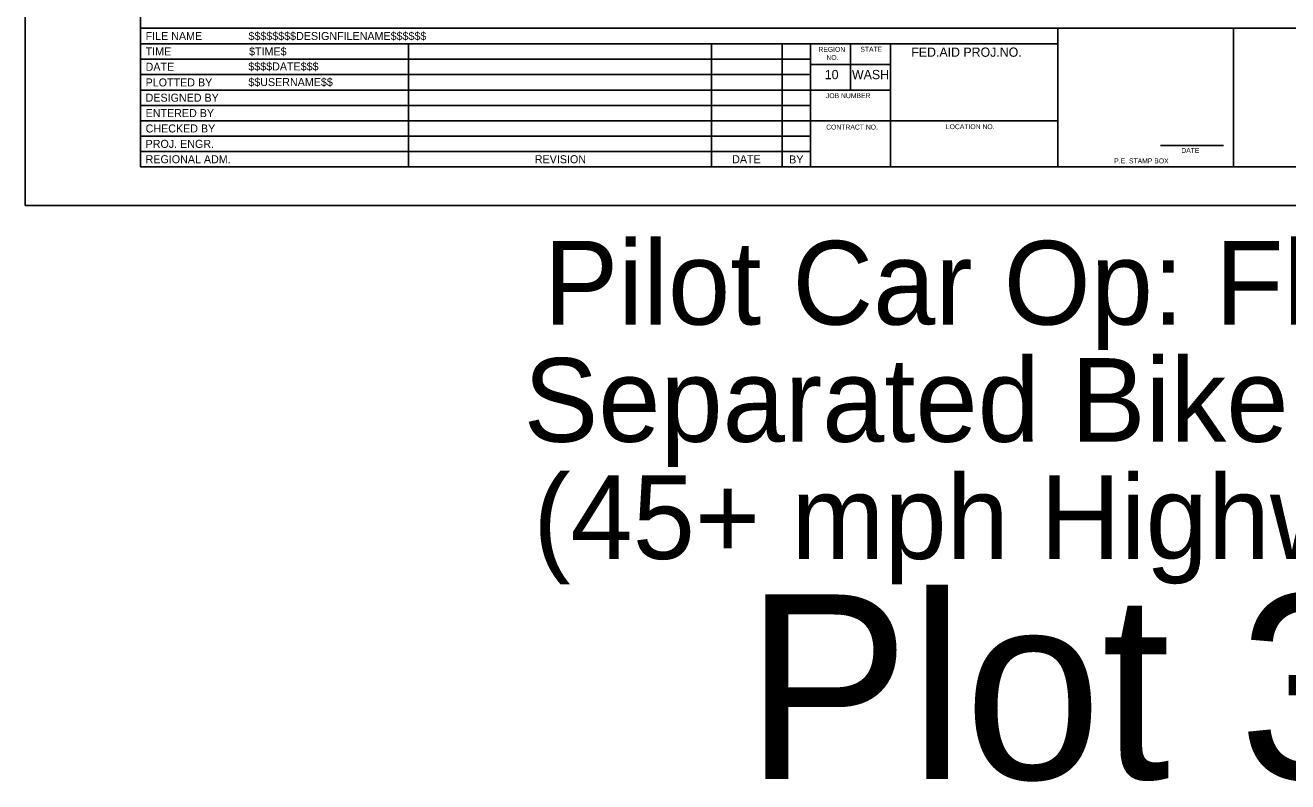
# Model space of a CAD drawing. Extents: x 99999.1 to 100095.7, y 99995 to 100010.7.
# Drawn here: x 100039.06 to 100049.33, y 99995.01 to 100001.15 of the extents above; entities that cross this region are included whole.
import ezdxf

# ---------------------------------------------------------------- set-up
doc = ezdxf.new("R2010")
doc.units = 0
for name, color, linetype in [('SH_GI_PlotLimits', 7, 'Continuous'), ('SH_GI_SheetBorder', 7, 'Continuous'), ('SH_GI_SheetLocationText', 7, 'Continuous'), ('SH_GI_SheetTextInCells', 7, 'Continuous'), ('SH_GI_TitleBlockText', 7, 'Continuous')]:
    doc.layers.add(name, color=color, linetype=linetype)

msp = doc.modelspace()

# ---------------------------------------------------------------- linework, layer by layer
at = {"layer": 'SH_GI_PlotLimits'}
msp.add_lwpolyline([(100039.062, 99999.687), (100056.062, 99999.687), (100056.062, 100010.687), (100039.062, 100010.687)], close=True, dxfattribs=at)
at = {"layer": 'SH_GI_SheetBorder'}
for p, q in [((100040, 100010.375), (100040, 100000)), ((100040, 100001.126), (100055.75, 100001.126)), ((100047.457, 100000), (100047.457, 100001.126)), ((100048.883, 100000), (100048.883, 100001.126)), ((100040, 100001.001), (100047.457, 100001.001)), ((100042.179, 100001.001), (100042.179, 100000)), ((100044.641, 100001.001), (100044.641, 100000)), ((100045.216, 100001.001), (100045.216, 100000)), ((100045.445, 100001.001), (100045.445, 100000)), ((100045.772, 100000.625), (100045.772, 100001.001)), ((100046.096, 100000), (100046.096, 100001.001)), ((100040, 100000.876), (100042.182, 100000.876)), ((100042.182, 100000.876), (100045.447, 100000.876)), ((100046.096, 100000.831), (100045.447, 100000.831)), ((100040, 100000.751), (100042.182, 100000.751)), ((100042.182, 100000.751), (100045.447, 100000.751)), ((100040, 100000.625), (100045.447, 100000.625)), ((100046.096, 100000.625), (100045.447, 100000.625)), ((100040, 100000.5), (100045.447, 100000.5)), ((100040, 100000.375), (100045.447, 100000.375)), ((100047.457, 100000.375), (100045.447, 100000.375)), ((100040, 100000.25), (100045.447, 100000.25)), ((100040, 100000.125), (100045.447, 100000.125)), ((100048.29, 100000.173), (100048.802, 100000.173)), ((100040, 100000), (100055.75, 100000))]:
    msp.add_line(p, q, dxfattribs=at)

# ---------------------------------------------------------------- texts
at = {"layer": 'SH_GI_SheetLocationText'}
for s, height, p in [('Pilot Car Op: Flagger', 0.68, (100043.277, 99998.719)), ('Separated Bike Lane', 0.68, (100043.114, 99997.767)), ('(45+ mph Highways)', 0.68, (100043.192, 99996.815)), ('Plot 3', 1.5, (100044.913, 99995.027))]:
    msp.add_text(s, height=height, dxfattribs=at).set_placement(p)
at = {"layer": 'SH_GI_SheetTextInCells'}
for s, height, p in [('FILE NAME', 0.0651, (100040.041, 100001.031)), ('TIME', 0.0651, (100040.041, 100000.906)), ('REGION', 0.04, (100045.51, 100000.935)), ('STATE', 0.04, (100045.851, 100000.936)), ('FED.AID PROJ.NO.', 0.07506, (100046.265, 100000.895)), ('DATE', 0.0651, (100040.041, 100000.781)), ('NO.', 0.04, (100045.575, 100000.869)), ('PLOTTED BY', 0.0651, (100040.041, 100000.654)), ('10', 0.0751, (100045.562, 100000.713)), ('WASH', 0.0751, (100045.783, 100000.713)), ('DESIGNED BY', 0.06505, (100040.041, 100000.53)), ('JOB NUMBER', 0.04, (100045.571, 100000.559)), ('ENTERED BY', 0.0651, (100040.041, 100000.405)), ('CHECKED BY', 0.0651, (100040.041, 100000.28)), ('CONTRACT NO.', 0.04003, (100045.573, 100000.304)), ('LOCATION NO.', 0.04003, (100046.546, 100000.307)), ('PROJ. ENGR.', 0.06505, (100040.041, 100000.155)), ('REGIONAL ADM.', 0.06505, (100040.041, 100000.03)), ('REVISION', 0.0651, (100043.205, 100000.03)), ('DATE', 0.0651, (100044.809, 100000.03)), ('BY', 0.0651, (100045.272, 100000.028)), ('DATE', 0.04, (100048.46, 100000.114)), ('P.E. STAMP BOX', 0.04003, (100047.915, 100000.029))]:
    msp.add_text(s, height=height, dxfattribs=at).set_placement(p)
at = {"layer": 'SH_GI_TitleBlockText'}
for s, height, p in [('$$$$$$$$DESIGNFILENAME$$$$$$', 0.06505, (100040.877, 100001.031)), ('$TIME$', 0.0651, (100040.882, 100000.906)), ('$$$$DATE$$$', 0.06505, (100040.876, 100000.784)), ('$$USERNAME$$', 0.06505, (100040.876, 100000.657))]:
    msp.add_text(s, height=height, dxfattribs=at).set_placement(p)

doc.saveas('drawing.dxf')
